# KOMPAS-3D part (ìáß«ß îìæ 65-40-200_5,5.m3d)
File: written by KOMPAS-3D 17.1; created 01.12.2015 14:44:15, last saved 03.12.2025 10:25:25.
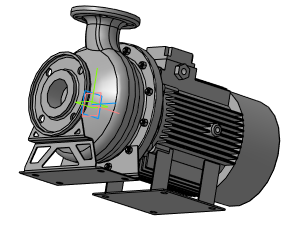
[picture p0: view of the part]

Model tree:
1. Операция без истории:3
